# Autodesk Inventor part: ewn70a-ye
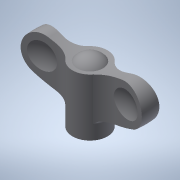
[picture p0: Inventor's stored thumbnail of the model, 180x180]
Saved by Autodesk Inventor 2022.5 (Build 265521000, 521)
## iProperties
Created: 2016-12
Part Number: ewn70a-ye
Material: 一般
Document SubType Name: Modeling
Designer: imaocorp
Density: 1 g/cm^3
Appearance: 既定
Author: imaocorp
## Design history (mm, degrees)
node "ewn70a-ye.x_t1"
node "ewn70a-ye"
node "Base1"
